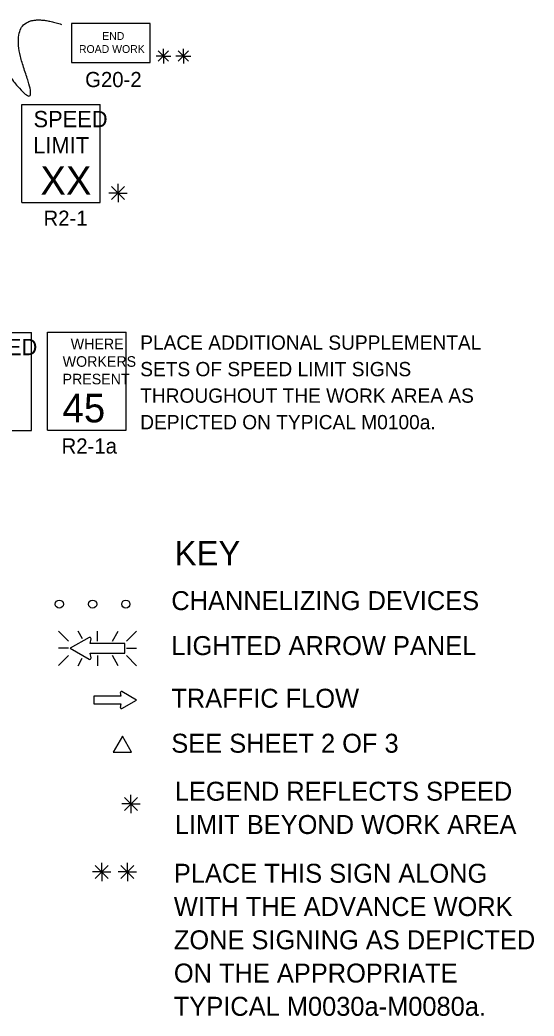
# Model space of a CAD drawing. Extents: x 16486 to 19506, y 5576 to 7023.
# Drawn here: x 17178.1 to 17429.8, y 6263.9 to 6752.1 of the extents above; entities that cross this region are included whole.
import ezdxf

# ---------------------------------------------------------------- set-up
doc = ezdxf.new("R2010")
doc.units = 0
for name, color, linetype in [('MT_SCRATCH_LEVEL_E', 7, 'Continuous'), ('TRAFFIC_SIGNS_PR', 7, 'Continuous'), ('TYPICAL_TEXT_DIMEN_EX', 7, 'Continuous'), ('TYPICAL_TEXT_DIMEN_PR', 7, 'Continuous')]:
    doc.layers.add(name, color=color, linetype=linetype)

msp = doc.modelspace()

# ---------------------------------------------------------------- linework, layer by layer
at = {"layer": 'MT_SCRATCH_LEVEL_E'}
for p, q in [((17227.59, 6420.68), (17214.34, 6420.68)), ((17214.34, 6420.68), (17214.34, 6416.93)), ((17227.28, 6422.45), (17227.59, 6420.68)), ((17235.2, 6418.82), (17227.96, 6422.93)), ((17214.34, 6416.93), (17227.59, 6416.93)), ((17227.59, 6416.93), (17227.28, 6415.16)), ((17227.96, 6414.68), (17235.2, 6418.82))]:
    msp.add_line(p, q, dxfattribs=at)
for centre, start, end in [((17227.74, 6422.53), 60.4248, 189.9638), ((17227.74, 6415.09), 170.0362, 299.7731)]:
    msp.add_arc(centre, 0.463, start, end, dxfattribs=at)
at = {"layer": 'TRAFFIC_SIGNS_PR'}
for p, q in [((17179.01, 6710.67), (17217.41, 6710.67)), ((17179.01, 6662.67), (17179.01, 6710.67)), ((17217.41, 6662.67), (17217.41, 6710.67)), ((17179.01, 6662.67), (17217.41, 6662.67)), ((17145.34, 6598.96), (17183.74, 6598.96)), ((17183.74, 6550.96), (17183.74, 6598.96)), ((17191.68, 6599.05), (17230.08, 6599.05)), ((17191.68, 6551.05), (17191.68, 6599.05)), ((17230.08, 6551.05), (17230.08, 6599.05)), ((17145.34, 6550.96), (17183.74, 6550.96)), ((17191.68, 6551.05), (17230.08, 6551.05)), ((17197.06, 6452.63), (17201.99, 6447.7)), ((17208.82, 6448.81), (17206.61, 6452.64)), ((17216.14, 6447.7), (17216.14, 6452.64)), ((17223.37, 6447.7), (17226.22, 6452.64)), ((17230.29, 6447.7), (17235.22, 6452.64)), ((17201.99, 6444.15), (17197.06, 6444.15)), ((17197.06, 6435.66), (17201.99, 6440.59)), ((17216.14, 6440.59), (17216.14, 6435.65)), ((17226.27, 6435.65), (17223.42, 6440.59)), ((17230.29, 6444.15), (17235.22, 6444.15)), ((17230.29, 6440.59), (17235.22, 6435.65)), ((17206.57, 6435.65), (17208.68, 6439.32))]:
    msp.add_line(p, q, dxfattribs=at)
msp.add_lwpolyline([(17203.43, 6731.22), (17241.83, 6731.22), (17241.83, 6750.42), (17203.43, 6750.42)], close=True, dxfattribs=at)
for points in [[(17212.07, 6449.42), (17202.77, 6444.15), (17212.07, 6438.82)], [(17212.94, 6439.45), (17212.54, 6441.72), (17229.55, 6441.72), (17229.55, 6446.52), (17212.54, 6446.52), (17212.94, 6448.8)]]:
    msp.add_lwpolyline(points, dxfattribs=at)
for centre in [(17197.4, 6465.83), (17213.7, 6465.83), (17230, 6465.83)]:
    msp.add_circle(centre, 2, dxfattribs=at)
for centre, radius, start, end in [((17212.35, 6448.9), 0.598, 350.7308, 118.8916), ((17212.35, 6439.35), 0.597, 241.4833, 9.9593)]:
    msp.add_arc(centre, radius, start, end, dxfattribs=at)
at = {"layer": 'TYPICAL_TEXT_DIMEN_PR'}
for p, q in [((17248.38, 6734.43), (17248.38, 6737.99)), ((17258.13, 6734.43), (17258.13, 6737.99)), ((17248.38, 6734.43), (17244.76, 6734.43)), ((17245.83, 6736.98), (17250.93, 6731.87)), ((17250.93, 6736.98), (17245.83, 6731.87)), ((17248.38, 6734.43), (17250.93, 6734.43)), ((17248.38, 6734.43), (17251.97, 6734.43)), ((17248.38, 6734.43), (17248.38, 6730.83)), ((17258.13, 6734.43), (17254.5, 6734.43)), ((17255.58, 6736.98), (17260.68, 6731.87)), ((17260.68, 6736.98), (17255.58, 6731.87)), ((17258.13, 6734.43), (17260.68, 6734.43)), ((17258.13, 6734.43), (17261.71, 6734.43)), ((17258.13, 6734.43), (17258.13, 6730.83)), ((17229.39, 6670.47), (17223.01, 6664.1)), ((17223.02, 6670.47), (17229.39, 6664.1)), ((17226.2, 6667.29), (17226.2, 6671.74)), ((17226.2, 6667.29), (17221.67, 6667.29)), ((17226.2, 6667.29), (17229.39, 6667.29)), ((17226.2, 6667.29), (17230.68, 6667.29)), ((17226.2, 6667.29), (17226.2, 6662.79)), ((17232.48, 6367.93), (17232.48, 6372.38)), ((17232.48, 6367.93), (17227.95, 6367.93)), ((17229.29, 6371.12), (17235.67, 6364.74)), ((17235.67, 6371.12), (17229.29, 6364.74)), ((17232.48, 6367.93), (17235.67, 6367.93)), ((17232.48, 6367.93), (17236.96, 6367.93)), ((17232.48, 6367.93), (17232.48, 6363.43)), ((17215, 6337.78), (17221.38, 6331.4)), ((17221.38, 6337.78), (17215, 6331.4)), ((17218.19, 6334.59), (17218.19, 6339.04)), ((17227.56, 6337.78), (17233.93, 6331.4)), ((17233.93, 6337.78), (17227.56, 6331.4)), ((17230.74, 6334.59), (17230.74, 6339.04)), ((17218.19, 6334.59), (17213.66, 6334.59)), ((17218.19, 6334.59), (17221.38, 6334.59)), ((17218.19, 6334.59), (17222.67, 6334.59)), ((17218.19, 6334.59), (17218.19, 6330.09)), ((17230.74, 6334.59), (17226.21, 6334.59)), ((17230.74, 6334.59), (17233.93, 6334.59)), ((17230.74, 6334.59), (17235.22, 6334.59)), ((17230.74, 6334.59), (17230.74, 6330.09))]:
    msp.add_line(p, q, dxfattribs=at)
msp.add_lwpolyline([(17228.27, 6401.12), (17223.75, 6393.28), (17232.8, 6393.28)], close=True, dxfattribs=at)
msp.add_open_spline([(17154.04, 6752.02), (17192.28, 6693.85), (17169.06, 6759.55), (17198.42, 6749.97)], degree=2, dxfattribs=at)

# ---------------------------------------------------------------- texts
at = {"layer": 'TRAFFIC_SIGNS_PR'}
for s, height, p in [('END', 3.831, (17218.43, 6742.34)), ('ROAD WORK', 3.831, (17207.04, 6735.96)), ('G20-2', 7.44, (17210.06, 6719.2)), ('SPEED', 8, (17184.78, 6699.53)), ('LIMIT', 8, (17184.62, 6686.73)), ('XX', 14.031, (17188.13, 6666.43)), ('R2-1', 7.44, (17189.69, 6651.23)), ('SPEED', 8, (17150.37, 6587.82)), ('WHERE', 5.2, (17202.99, 6590.73)), ('PLACE ADDITIONAL SUPPLEMENTAL', 7, (17237.02, 6590.5)), ('WORKERS', 5.2, (17199.06, 6582.13)), ('SETS OF SPEED LIMIT SIGNS', 7, (17237.02, 6577.5)), ('PRESENT', 5.2, (17199, 6573.53)), ('THROUGHOUT THE WORK AREA AS', 7, (17237.02, 6564.5)), ('45', 14.031, (17198.99, 6554.9)), ('DEPICTED ON TYPICAL M0100a.', 7, (17237.02, 6551.5)), ('R2-1a', 7.44, (17198.53, 6539.61))]:
    msp.add_text(s, height=height, dxfattribs=at).set_placement(p)
at = {"layer": 'TYPICAL_TEXT_DIMEN_EX'}
for s, height, p in [('KEY', 12, (17253.9, 6484.8)), ('CHANNELIZING DEVICES', 9.3, (17252.24, 6462.89)), ('LIGHTED ARROW PANEL', 9.3, (17252.24, 6440.84)), ('TRAFFIC FLOW', 9.3, (17252.24, 6415.04)), ('SEE SHEET 2 OF 3', 9.3, (17252.24, 6392.99)), ('LEGEND REFLECTS SPEED', 9.3, (17253.93, 6369.46)), ('LIMIT BEYOND WORK AREA', 9.3, (17253.93, 6353.16)), ('PLACE THIS SIGN ALONG', 9.3, (17253.48, 6329.25)), ('WITH THE ADVANCE WORK', 9.3, (17253.48, 6312.95)), ('ZONE SIGNING AS DEPICTED', 9.3, (17253.48, 6296.65)), ('ON THE APPROPRIATE', 9.3, (17253.48, 6280.35)), ('TYPICAL M0030a-M0080a.', 9.3, (17253.48, 6264.05))]:
    msp.add_text(s, height=height, dxfattribs=at).set_placement(p)

doc.saveas('drawing.dxf')
